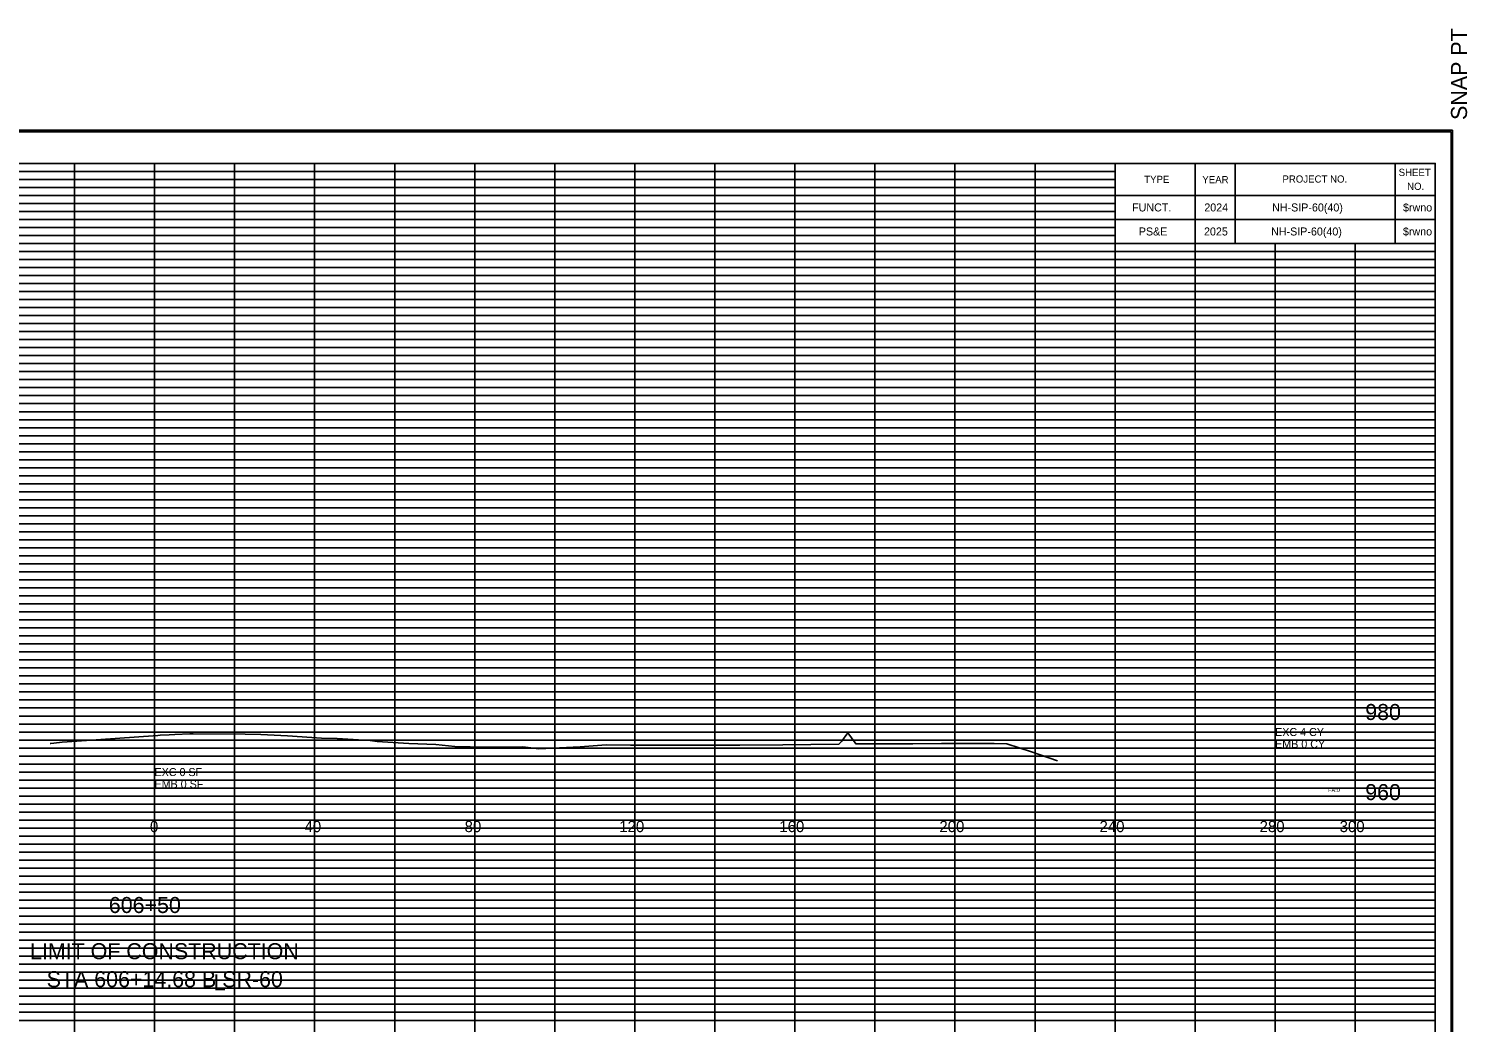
# Model space of a CAD drawing. Extents: x 2313580 to 2322968, y 282099 to 303247.
# Drawn here: x 2320334.7 to 2320694.1, y 287793.2 to 288041.3 of the extents above; entities that cross this region are included whole.
import ezdxf

# ---------------------------------------------------------------- set-up
doc = ezdxf.new("R2010")
doc.units = 0
for name, color, linetype in [('DESIGN - EARTHWORK - Excavation Limit Lines', 7, 'Continuous'), ('DESIGN - SCRATCH - User 1', 7, 'Continuous'), ('DESIGN - SHEET - Corner Text', 7, 'Continuous'), ('DESIGN - SHEET - Light Grid', 7, 'Continuous'), ('DESIGN - SHEET - Linework', 7, 'Continuous'), ('DESIGN - SHEET - Plot Shape', 7, 'Continuous'), ('DESIGN - TYPICAL - Text', 7, 'Continuous'), ('Prop_ CL text', 7, 'Continuous'), ('SURVEY - GROUND - Top of Ground', 7, 'Continuous')]:
    doc.layers.add(name, color=color, linetype=linetype)

msp = doc.modelspace()

# ---------------------------------------------------------------- linework, layer by layer
at = {"layer": 'DESIGN - SCRATCH - User 1'}
for p, q in [((2320616.08, 287996.67), (2320616.08, 287996.67)), ((2320630.88, 287996.67), (2320630.88, 287996.67)), ((2320655.88, 287996.67), (2320655.88, 287996.67)), ((2320680.88, 287996.67), (2320680.88, 287996.67)), ((2320616.08, 287990.67), (2320616.08, 287990.67)), ((2320630.88, 287990.67), (2320630.88, 287990.67)), ((2320655.88, 287990.67), (2320655.88, 287990.67)), ((2320680.88, 287990.67), (2320680.88, 287990.67))]:
    msp.add_line(p, q, dxfattribs=at)
at = {"layer": 'DESIGN - SHEET - Light Grid'}
for p, q in [((2320206.08, 288005.67), (2320366.08, 288005.67)), ((2320366.08, 288005.67), (2320526.08, 288005.67)), ((2320526.08, 288005.67), (2320606.08, 288005.67)), ((2320206.08, 288003.67), (2320366.08, 288003.67)), ((2320206.08, 288001.67), (2320366.08, 288001.67)), ((2320366.08, 288003.67), (2320526.08, 288003.67)), ((2320366.08, 288001.67), (2320526.08, 288001.67)), ((2320526.08, 288003.67), (2320606.08, 288003.67)), ((2320526.08, 288001.67), (2320606.08, 288001.67)), ((2320206.08, 287999.67), (2320366.08, 287999.67)), ((2320206.08, 287997.67), (2320366.08, 287997.67)), ((2320366.08, 287999.67), (2320526.08, 287999.67)), ((2320366.08, 287997.67), (2320526.08, 287997.67)), ((2320526.08, 287999.67), (2320606.08, 287999.67)), ((2320526.08, 287997.67), (2320606.08, 287997.67)), ((2320206.08, 287995.67), (2320366.08, 287995.67)), ((2320206.08, 287993.67), (2320366.08, 287993.67)), ((2320366.08, 287995.67), (2320526.08, 287995.67)), ((2320366.08, 287993.67), (2320526.08, 287993.67)), ((2320526.08, 287995.67), (2320606.08, 287995.67)), ((2320526.08, 287993.67), (2320606.08, 287993.67)), ((2320206.08, 287991.67), (2320366.08, 287991.67)), ((2320206.08, 287989.67), (2320366.08, 287989.67)), ((2320366.08, 287991.67), (2320526.08, 287991.67)), ((2320366.08, 287989.67), (2320526.08, 287989.67)), ((2320526.08, 287991.67), (2320606.08, 287991.67)), ((2320526.08, 287989.67), (2320606.08, 287989.67)), ((2320206.08, 287985.67), (2320366.08, 287985.67)), ((2320206.08, 287983.67), (2320366.08, 287983.67)), ((2320366.08, 287985.67), (2320526.08, 287985.67)), ((2320366.08, 287983.67), (2320526.08, 287983.67)), ((2320526.08, 287985.67), (2320686.08, 287985.67)), ((2320526.08, 287983.67), (2320686.08, 287983.67)), ((2320206.08, 287981.67), (2320366.08, 287981.67)), ((2320206.08, 287979.67), (2320366.08, 287979.67)), ((2320366.08, 287981.67), (2320526.08, 287981.67)), ((2320366.08, 287979.67), (2320526.08, 287979.67)), ((2320526.08, 287981.67), (2320686.08, 287981.67)), ((2320526.08, 287979.67), (2320686.08, 287979.67)), ((2320206.08, 287977.67), (2320366.08, 287977.67)), ((2320206.08, 287975.67), (2320366.08, 287975.67)), ((2320366.08, 287977.67), (2320526.08, 287977.67)), ((2320366.08, 287975.67), (2320526.08, 287975.67)), ((2320526.08, 287977.67), (2320686.08, 287977.67)), ((2320526.08, 287975.67), (2320686.08, 287975.67)), ((2320206.08, 287973.67), (2320366.08, 287973.67)), ((2320206.08, 287971.67), (2320366.08, 287971.67)), ((2320366.08, 287973.67), (2320526.08, 287973.67)), ((2320366.08, 287971.67), (2320526.08, 287971.67)), ((2320526.08, 287973.67), (2320686.08, 287973.67)), ((2320526.08, 287971.67), (2320686.08, 287971.67)), ((2320206.08, 287969.67), (2320366.08, 287969.67)), ((2320366.08, 287969.67), (2320526.08, 287969.67)), ((2320526.08, 287969.67), (2320686.08, 287969.67)), ((2320206.08, 287965.67), (2320366.08, 287965.67)), ((2320366.08, 287965.67), (2320526.08, 287965.67)), ((2320526.08, 287965.67), (2320686.08, 287965.67)), ((2320206.08, 287963.67), (2320366.08, 287963.67)), ((2320206.08, 287961.67), (2320366.08, 287961.67)), ((2320366.08, 287963.67), (2320526.08, 287963.67)), ((2320366.08, 287961.67), (2320526.08, 287961.67)), ((2320526.08, 287963.67), (2320686.08, 287963.67)), ((2320526.08, 287961.67), (2320686.08, 287961.67)), ((2320206.08, 287959.67), (2320366.08, 287959.67)), ((2320206.08, 287957.67), (2320366.08, 287957.67)), ((2320366.08, 287959.67), (2320526.08, 287959.67)), ((2320366.08, 287957.67), (2320526.08, 287957.67)), ((2320526.08, 287959.67), (2320686.08, 287959.67)), ((2320526.08, 287957.67), (2320686.08, 287957.67)), ((2320206.08, 287955.67), (2320366.08, 287955.67)), ((2320206.08, 287953.67), (2320366.08, 287953.67)), ((2320366.08, 287955.67), (2320526.08, 287955.67)), ((2320366.08, 287953.67), (2320526.08, 287953.67)), ((2320526.08, 287955.67), (2320686.08, 287955.67)), ((2320526.08, 287953.67), (2320686.08, 287953.67)), ((2320206.08, 287951.67), (2320366.08, 287951.67)), ((2320366.08, 287951.67), (2320526.08, 287951.67)), ((2320526.08, 287951.67), (2320686.08, 287951.67)), ((2320206.08, 287949.67), (2320366.08, 287949.67)), ((2320366.08, 287949.67), (2320526.08, 287949.67)), ((2320526.08, 287949.67), (2320686.08, 287949.67)), ((2320206.08, 287945.67), (2320366.08, 287945.67)), ((2320206.08, 287943.67), (2320366.08, 287943.67)), ((2320366.08, 287945.67), (2320526.08, 287945.67)), ((2320366.08, 287943.67), (2320526.08, 287943.67)), ((2320526.08, 287945.67), (2320686.08, 287945.67)), ((2320526.08, 287943.67), (2320686.08, 287943.67)), ((2320206.08, 287941.67), (2320366.08, 287941.67)), ((2320206.08, 287939.67), (2320366.08, 287939.67)), ((2320366.08, 287941.67), (2320526.08, 287941.67)), ((2320366.08, 287939.67), (2320526.08, 287939.67)), ((2320526.08, 287941.67), (2320686.08, 287941.67)), ((2320526.08, 287939.67), (2320686.08, 287939.67)), ((2320206.08, 287937.67), (2320366.08, 287937.67)), ((2320206.08, 287935.67), (2320366.08, 287935.67)), ((2320366.08, 287937.67), (2320526.08, 287937.67)), ((2320366.08, 287935.67), (2320526.08, 287935.67)), ((2320526.08, 287937.67), (2320686.08, 287937.67)), ((2320526.08, 287935.67), (2320686.08, 287935.67)), ((2320206.08, 287933.67), (2320366.08, 287933.67)), ((2320366.08, 287933.67), (2320526.08, 287933.67)), ((2320526.08, 287933.67), (2320686.08, 287933.67)), ((2320206.08, 287931.67), (2320366.08, 287931.67)), ((2320206.08, 287929.67), (2320366.08, 287929.67)), ((2320366.08, 287931.67), (2320526.08, 287931.67)), ((2320366.08, 287929.67), (2320526.08, 287929.67)), ((2320526.08, 287931.67), (2320686.08, 287931.67)), ((2320526.08, 287929.67), (2320686.08, 287929.67)), ((2320206.08, 287925.67), (2320366.08, 287925.67)), ((2320366.08, 287925.67), (2320526.08, 287925.67)), ((2320526.08, 287925.67), (2320686.08, 287925.67)), ((2320206.08, 287923.67), (2320366.08, 287923.67)), ((2320206.08, 287921.67), (2320366.08, 287921.67)), ((2320366.08, 287923.67), (2320526.08, 287923.67)), ((2320366.08, 287921.67), (2320526.08, 287921.67)), ((2320526.08, 287923.67), (2320686.08, 287923.67)), ((2320526.08, 287921.67), (2320686.08, 287921.67)), ((2320206.08, 287919.67), (2320366.08, 287919.67)), ((2320206.08, 287917.67), (2320366.08, 287917.67)), ((2320366.08, 287919.67), (2320526.08, 287919.67)), ((2320366.08, 287917.67), (2320526.08, 287917.67)), ((2320526.08, 287919.67), (2320686.08, 287919.67)), ((2320526.08, 287917.67), (2320686.08, 287917.67)), ((2320206.08, 287915.67), (2320366.08, 287915.67)), ((2320366.08, 287915.67), (2320526.08, 287915.67)), ((2320526.08, 287915.67), (2320686.08, 287915.67)), ((2320206.08, 287913.67), (2320366.08, 287913.67)), ((2320206.08, 287911.67), (2320366.08, 287911.67)), ((2320366.08, 287913.67), (2320526.08, 287913.67)), ((2320366.08, 287911.67), (2320526.08, 287911.67)), ((2320526.08, 287913.67), (2320686.08, 287913.67)), ((2320526.08, 287911.67), (2320686.08, 287911.67)), ((2320206.08, 287909.67), (2320366.08, 287909.67)), ((2320366.08, 287909.67), (2320526.08, 287909.67)), ((2320526.08, 287909.67), (2320686.08, 287909.67)), ((2320206.08, 287905.67), (2320366.08, 287905.67)), ((2320206.08, 287903.67), (2320366.08, 287903.67)), ((2320366.08, 287905.67), (2320526.08, 287905.67)), ((2320366.08, 287903.67), (2320526.08, 287903.67)), ((2320526.08, 287905.67), (2320686.08, 287905.67)), ((2320526.08, 287903.67), (2320686.08, 287903.67)), ((2320206.08, 287901.67), (2320366.08, 287901.67)), ((2320206.08, 287899.67), (2320366.08, 287899.67)), ((2320366.08, 287901.67), (2320526.08, 287901.67)), ((2320366.08, 287899.67), (2320526.08, 287899.67)), ((2320526.08, 287901.67), (2320686.08, 287901.67)), ((2320526.08, 287899.67), (2320686.08, 287899.67)), ((2320206.08, 287897.67), (2320366.08, 287897.67)), ((2320366.08, 287897.67), (2320526.08, 287897.67)), ((2320526.08, 287897.67), (2320686.08, 287897.67)), ((2320206.08, 287895.67), (2320366.08, 287895.67)), ((2320206.08, 287893.67), (2320366.08, 287893.67)), ((2320366.08, 287895.67), (2320526.08, 287895.67)), ((2320366.08, 287893.67), (2320526.08, 287893.67)), ((2320526.08, 287895.67), (2320686.08, 287895.67)), ((2320526.08, 287893.67), (2320686.08, 287893.67)), ((2320206.08, 287891.67), (2320366.08, 287891.67)), ((2320206.08, 287889.67), (2320366.08, 287889.67)), ((2320366.08, 287891.67), (2320526.08, 287891.67)), ((2320366.08, 287889.67), (2320526.08, 287889.67)), ((2320526.08, 287891.67), (2320686.08, 287891.67)), ((2320526.08, 287889.67), (2320686.08, 287889.67)), ((2320206.08, 287885.67), (2320366.08, 287885.67)), ((2320366.08, 287885.67), (2320526.08, 287885.67)), ((2320526.08, 287885.67), (2320686.08, 287885.67)), ((2320206.08, 287883.67), (2320366.08, 287883.67)), ((2320206.08, 287881.67), (2320366.08, 287881.67)), ((2320366.08, 287883.67), (2320526.08, 287883.67)), ((2320366.08, 287881.67), (2320526.08, 287881.67)), ((2320526.08, 287883.67), (2320686.08, 287883.67)), ((2320526.08, 287881.67), (2320686.08, 287881.67)), ((2320206.08, 287879.67), (2320366.08, 287879.67)), ((2320366.08, 287879.67), (2320526.08, 287879.67)), ((2320526.08, 287879.67), (2320686.08, 287879.67)), ((2320206.08, 287877.67), (2320366.08, 287877.67)), ((2320206.08, 287875.67), (2320366.08, 287875.67)), ((2320366.08, 287877.67), (2320526.08, 287877.67)), ((2320366.08, 287875.67), (2320526.08, 287875.67)), ((2320526.08, 287877.67), (2320686.08, 287877.67)), ((2320526.08, 287875.67), (2320686.08, 287875.67)), ((2320206.08, 287873.67), (2320366.08, 287873.67)), ((2320206.08, 287871.67), (2320366.08, 287871.67)), ((2320366.08, 287873.67), (2320526.08, 287873.67)), ((2320366.08, 287871.67), (2320526.08, 287871.67)), ((2320526.08, 287873.67), (2320686.08, 287873.67)), ((2320526.08, 287871.67), (2320686.08, 287871.67)), ((2320206.08, 287869.67), (2320366.08, 287869.67)), ((2320366.08, 287869.67), (2320526.08, 287869.67)), ((2320526.08, 287869.67), (2320686.08, 287869.67)), ((2320206.08, 287865.67), (2320366.08, 287865.67)), ((2320206.08, 287863.67), (2320366.08, 287863.67)), ((2320366.08, 287865.67), (2320526.08, 287865.67)), ((2320366.08, 287863.67), (2320526.08, 287863.67)), ((2320526.08, 287865.67), (2320686.08, 287865.67)), ((2320526.08, 287863.67), (2320686.08, 287863.67)), ((2320206.08, 287861.67), (2320366.08, 287861.67)), ((2320366.08, 287861.67), (2320526.08, 287861.67)), ((2320526.08, 287861.67), (2320686.08, 287861.67)), ((2320206.08, 287859.67), (2320366.08, 287859.67)), ((2320206.08, 287857.67), (2320366.08, 287857.67)), ((2320366.08, 287859.67), (2320526.08, 287859.67)), ((2320366.08, 287857.67), (2320526.08, 287857.67)), ((2320526.08, 287859.67), (2320686.08, 287859.67)), ((2320526.08, 287857.67), (2320686.08, 287857.67)), ((2320206.08, 287855.67), (2320366.08, 287855.67)), ((2320206.08, 287853.67), (2320366.08, 287853.67)), ((2320366.08, 287855.67), (2320526.08, 287855.67)), ((2320366.08, 287853.67), (2320526.08, 287853.67)), ((2320526.08, 287855.67), (2320686.08, 287855.67)), ((2320526.08, 287853.67), (2320686.08, 287853.67)), ((2320206.08, 287851.67), (2320366.08, 287851.67)), ((2320206.08, 287849.67), (2320366.08, 287849.67)), ((2320366.08, 287851.67), (2320526.08, 287851.67)), ((2320366.08, 287849.67), (2320526.08, 287849.67)), ((2320526.08, 287851.67), (2320686.08, 287851.67)), ((2320526.08, 287849.67), (2320686.08, 287849.67)), ((2320206.08, 287845.67), (2320366.08, 287845.67)), ((2320206.08, 287843.67), (2320366.08, 287843.67)), ((2320366.08, 287845.67), (2320526.08, 287845.67)), ((2320366.08, 287843.67), (2320526.08, 287843.67)), ((2320526.08, 287845.67), (2320686.08, 287845.67)), ((2320526.08, 287843.67), (2320686.08, 287843.67)), ((2320206.08, 287841.67), (2320366.08, 287841.67)), ((2320206.08, 287839.67), (2320366.08, 287839.67)), ((2320366.08, 287841.67), (2320526.08, 287841.67)), ((2320366.08, 287839.67), (2320526.08, 287839.67)), ((2320526.08, 287841.67), (2320686.08, 287841.67)), ((2320526.08, 287839.67), (2320686.08, 287839.67)), ((2320206.08, 287837.67), (2320366.08, 287837.67)), ((2320206.08, 287835.67), (2320366.08, 287835.67)), ((2320366.08, 287837.67), (2320526.08, 287837.67)), ((2320366.08, 287835.67), (2320526.08, 287835.67)), ((2320526.08, 287837.67), (2320686.08, 287837.67)), ((2320526.08, 287835.67), (2320686.08, 287835.67)), ((2320206.08, 287833.67), (2320366.08, 287833.67)), ((2320206.08, 287831.67), (2320366.08, 287831.67)), ((2320366.08, 287833.67), (2320526.08, 287833.67)), ((2320366.08, 287831.67), (2320526.08, 287831.67)), ((2320526.08, 287833.67), (2320686.08, 287833.67)), ((2320526.08, 287831.67), (2320686.08, 287831.67)), ((2320206.08, 287829.67), (2320366.08, 287829.67)), ((2320366.08, 287829.67), (2320526.08, 287829.67)), ((2320526.08, 287829.67), (2320686.08, 287829.67)), ((2320206.08, 287825.67), (2320366.08, 287825.67)), ((2320366.08, 287825.67), (2320526.08, 287825.67)), ((2320526.08, 287825.67), (2320686.08, 287825.67)), ((2320206.08, 287823.67), (2320366.08, 287823.67)), ((2320206.08, 287821.67), (2320366.08, 287821.67)), ((2320366.08, 287823.67), (2320526.08, 287823.67)), ((2320366.08, 287821.67), (2320526.08, 287821.67)), ((2320526.08, 287823.67), (2320686.08, 287823.67)), ((2320526.08, 287821.67), (2320686.08, 287821.67)), ((2320206.08, 287819.67), (2320366.08, 287819.67)), ((2320206.08, 287817.67), (2320366.08, 287817.67)), ((2320366.08, 287819.67), (2320526.08, 287819.67)), ((2320366.08, 287817.67), (2320526.08, 287817.67)), ((2320526.08, 287819.67), (2320686.08, 287819.67)), ((2320526.08, 287817.67), (2320686.08, 287817.67)), ((2320206.08, 287815.67), (2320366.08, 287815.67)), ((2320206.08, 287813.67), (2320366.08, 287813.67)), ((2320366.08, 287815.67), (2320526.08, 287815.67)), ((2320366.08, 287813.67), (2320526.08, 287813.67)), ((2320526.08, 287815.67), (2320686.08, 287815.67)), ((2320526.08, 287813.67), (2320686.08, 287813.67)), ((2320206.08, 287811.67), (2320366.08, 287811.67)), ((2320366.08, 287811.67), (2320526.08, 287811.67)), ((2320526.08, 287811.67), (2320686.08, 287811.67)), ((2320206.08, 287809.67), (2320366.08, 287809.67)), ((2320366.08, 287809.67), (2320526.08, 287809.67)), ((2320526.08, 287809.67), (2320686.08, 287809.67)), ((2320206.08, 287805.67), (2320366.08, 287805.67)), ((2320206.08, 287803.67), (2320366.08, 287803.67)), ((2320366.08, 287805.67), (2320526.08, 287805.67)), ((2320366.08, 287803.67), (2320526.08, 287803.67)), ((2320526.08, 287805.67), (2320686.08, 287805.67)), ((2320526.08, 287803.67), (2320686.08, 287803.67)), ((2320206.08, 287801.67), (2320366.08, 287801.67)), ((2320206.08, 287799.67), (2320366.08, 287799.67)), ((2320366.08, 287801.67), (2320526.08, 287801.67)), ((2320366.08, 287799.67), (2320526.08, 287799.67)), ((2320526.08, 287801.67), (2320686.08, 287801.67)), ((2320526.08, 287799.67), (2320686.08, 287799.67)), ((2320206.08, 287797.67), (2320366.08, 287797.67)), ((2320206.08, 287795.67), (2320366.08, 287795.67)), ((2320366.08, 287797.67), (2320526.08, 287797.67)), ((2320366.08, 287795.67), (2320526.08, 287795.67)), ((2320526.08, 287797.67), (2320686.08, 287797.67)), ((2320526.08, 287795.67), (2320686.08, 287795.67)), ((2320206.08, 287793.67), (2320366.08, 287793.67)), ((2320366.08, 287793.67), (2320526.08, 287793.67)), ((2320526.08, 287793.67), (2320686.08, 287793.67))]:
    msp.add_line(p, q, dxfattribs=at)
at = {"layer": 'DESIGN - SHEET - Linework'}
for p, q in [((2320009.62, 288015.95), (2320690.42, 288015.95)), ((2320690.42, 288015.95), (2320690.42, 287579.39)), ((2320346.08, 287587.67), (2320346.08, 288007.67)), ((2320366.08, 287587.67), (2320366.08, 288007.67)), ((2320386.08, 287587.67), (2320386.08, 288007.67)), ((2320406.08, 287587.67), (2320406.08, 288007.67)), ((2320426.08, 287587.67), (2320426.08, 288007.67)), ((2320446.08, 287587.67), (2320446.08, 288007.67)), ((2320466.08, 287587.67), (2320466.08, 288007.67)), ((2320486.08, 287587.67), (2320486.08, 288007.67)), ((2320506.08, 287587.67), (2320506.08, 288007.67)), ((2320526.08, 287587.67), (2320526.08, 288007.67)), ((2320546.08, 287587.67), (2320546.08, 288007.67)), ((2320566.08, 287587.67), (2320566.08, 288007.67)), ((2320586.08, 287587.67), (2320586.08, 288007.67)), ((2320046.08, 287987.67), (2320606.08, 287987.67)), ((2320606.08, 287587.67), (2320606.08, 287987.67)), ((2320626.08, 287587.67), (2320626.08, 287987.67)), ((2320646.08, 287587.67), (2320646.08, 287987.67)), ((2320666.08, 287587.67), (2320666.08, 287987.67)), ((2320046.08, 287967.67), (2320686.08, 287967.67)), ((2320046.08, 287947.67), (2320686.08, 287947.67)), ((2320046.08, 287927.67), (2320686.08, 287927.67)), ((2320046.08, 287907.67), (2320686.08, 287907.67)), ((2320046.08, 287887.67), (2320686.08, 287887.67)), ((2320046.08, 287867.67), (2320686.08, 287867.67)), ((2320046.08, 287847.67), (2320686.08, 287847.67)), ((2320046.08, 287827.67), (2320686.08, 287827.67)), ((2320046.08, 287807.67), (2320686.08, 287807.67))]:
    msp.add_line(p, q, dxfattribs=at)
for points in [[(2320046.08, 288007.67), (2320046.08, 287587.67), (2320686.08, 287587.67), (2320686.08, 288007.67), (2320046.08, 288007.67)], [(2320606.08, 288007.67), (2320606.08, 287987.67), (2320686.08, 287987.67), (2320686.08, 288007.67), (2320676.08, 288007.67), (2320676.08, 287987.67), (2320636.08, 287987.67), (2320636.08, 288007.67), (2320626.08, 288007.67), (2320626.08, 287987.67), (2320686.08, 287987.67), (2320606.08, 287987.67), (2320606.08, 287993.67), (2320686.08, 287993.67), (2320686.08, 287999.67), (2320606.08, 287999.67)]]:
    msp.add_lwpolyline(points, dxfattribs=at)
at = {"layer": 'DESIGN - SHEET - Plot Shape'}
for points in [[(2320010.02, 288015.55), (2320690.02, 288015.55), (2320690.02, 287579.79), (2320010.02, 287579.79)], [(2320029.08, 288007.67), (2320686.08, 288007.67), (2320686.08, 287582.67), (2320029.08, 287582.67)]]:
    msp.add_lwpolyline(points, close=True, dxfattribs=at)
at = {"layer": 'SURVEY - GROUND - Top of Ground'}
msp.add_lwpolyline([(2320340, 287862.83), (2320340.14, 287862.83), (2320342.34, 287863.08), (2320343.03, 287863.14), (2320351.47, 287863.74), (2320366.93, 287864.82), (2320367.46, 287864.85), (2320369.76, 287864.96), (2320371.13, 287865.02), (2320374.9, 287865.21), (2320375.77, 287865.23), (2320388.7, 287865.1), (2320392.63, 287865.02), (2320399.28, 287864.69), (2320407.83, 287864.17), (2320411.69, 287864.01), (2320417.02, 287863.74), (2320419.98, 287863.53), (2320421.69, 287863.32), (2320429.61, 287862.8), (2320436.4, 287862.59), (2320441.14, 287862.02), (2320448.84, 287861.88), (2320458.12, 287861.95), (2320462.13, 287861.45), (2320472.43, 287862), (2320473.5, 287862.05), (2320478.91, 287862.44), (2320485.04, 287862.4), (2320488.1, 287862.4), (2320497.86, 287862.37), (2320505.56, 287862.41), (2320509.78, 287862.4), (2320510.46, 287862.4), (2320512.36, 287862.41), (2320523.07, 287862.44), (2320537.09, 287862.62), (2320537.74, 287863.34), (2320539.34, 287865.46), (2320541.13, 287863.01), (2320541.33, 287862.69), (2320541.47, 287862.7), (2320542.12, 287862.69), (2320544.46, 287862.7), (2320555.59, 287862.71), (2320562.7, 287862.79), (2320566.99, 287862.83), (2320575.88, 287862.77), (2320579.04, 287862.75), (2320585.21, 287860.72), (2320591.69, 287858.48)], dxfattribs=at)

# ---------------------------------------------------------------- texts
at = {"layer": 'DESIGN - EARTHWORK - Excavation Limit Lines'}
for s, p in [('EXC 4 CY', (2320646.08, 287864.67)), ('EMB 0 CY', (2320646.08, 287861.67)), ('EXC 0 SF', (2320366.08, 287854.67)), ('EMB 0 SF', (2320366.08, 287851.67))]:
    msp.add_text(s, height=2, dxfattribs=at).set_placement(p)
at = {"layer": 'DESIGN - SHEET - Corner Text'}
for s, height, rotation, p in [('  SNAP PT', 4, 90, (2320694.02, 288015.55)), ('TYPE', 1.8, 360, (2320613.36, 288002.79)), ('YEAR', 1.8, 360, (2320627.89, 288002.71)), ('PROJECT NO.', 1.8, 360, (2320647.9, 288002.87)), ('SHEET', 1.8, 360, (2320676.94, 288004.53)), ('NO.', 1.8, 360, (2320679.05, 288001.05)), ('  FUNCT.   ', 2, 360, (2320608.85, 287995.67)), ('2024', 2, 360, (2320628.38, 287995.67)), ('$rwno', 2, 360, (2320678.03, 287995.67))]:
    msp.add_text(s, height=height, rotation=rotation, dxfattribs=at).set_placement(p)
for s, p in [('   NH-SIP-60(40)    ', (2320643.09, 287995.67)), (' PS&E ', (2320611.27, 287989.67)), ('2025', (2320628.3, 287989.67)), ('   NH-SIP-60(40)    ', (2320642.84, 287989.67)), ('$rwno', (2320678.01, 287989.67))]:
    msp.add_text(s, height=2, dxfattribs=at).set_placement(p)
at = {"layer": 'DESIGN - TYPICAL - Text'}
for s, height, p in [('980', 4, (2320668.58, 287868.67)), ('960', 4, (2320668.58, 287848.67)), ('0', 2.8, (2320364.92, 287840.67)), ('40', 2.8, (2320403.55, 287840.67)), ('80', 2.8, (2320443.55, 287840.67)), ('120', 2.8, (2320482.19, 287840.67)), ('160', 2.8, (2320522.19, 287840.67)), ('200', 2.8, (2320562.19, 287840.67)), ('240', 2.8, (2320602.19, 287840.67)), ('280', 2.8, (2320642.19, 287840.67)), ('300', 2.8, (2320662.19, 287840.67)), ('606+50', 4, (2320354.66, 287820.47)), ('LIMIT OF CONSTRUCTION', 4, (2320334.96, 287808.94)), ('STA 606+14.68 B SR-60', 4, (2320339.12, 287801.94)), ('L', 4, (2320380.86, 287801.16))]:
    msp.add_text(s, height=height, dxfattribs=at).set_placement(p)
at = {"layer": 'Prop_ CL text'}
msp.add_text('FA:0', height=1, dxfattribs=at).set_placement((2320659.32, 287850.67))

doc.saveas('drawing.dxf')
